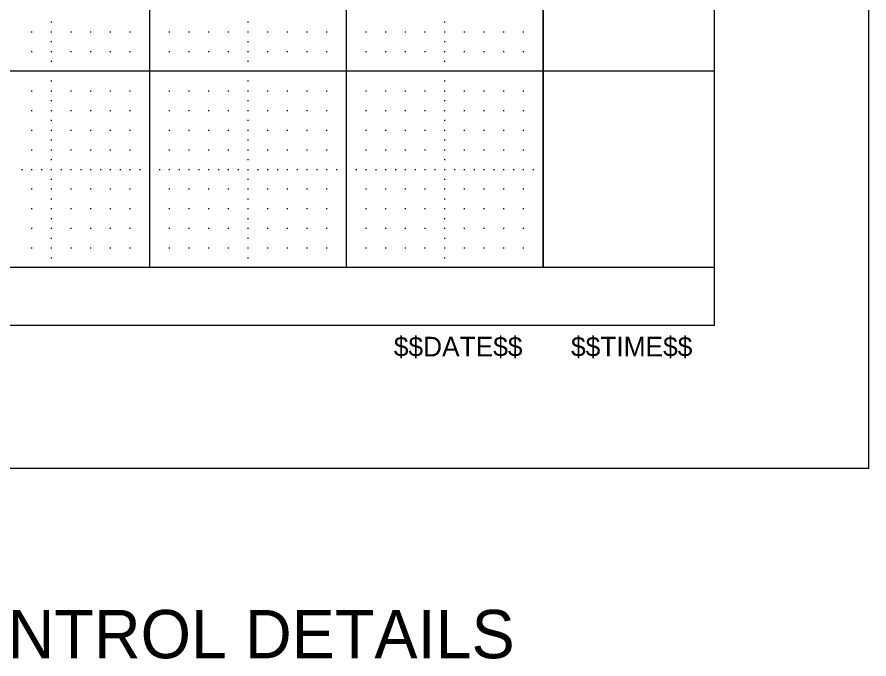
# Model space of a CAD drawing. Extents: x -1.6 to 32.7, y -1.7 to 21.9.
# Drawn here: x 28.07 to 32.402, y -1.698 to 1.568 of the extents above; entities that cross this region are included whole.
import ezdxf

# ---------------------------------------------------------------- set-up
doc = ezdxf.new("R2010")
doc.units = 0
for name, color, linetype in [('Level 1', 7, 'Continuous'), ('Level 4', 7, 'Continuous'), ('Level 48', 7, 'Continuous'), ('Level 5', 7, 'Continuous'), ('Level 63', 7, 'Continuous'), ('R_Border_Dark', 7, 'Continuous'), ('TYPICAL FONT', 7, 'Continuous')]:
    doc.layers.add(name, color=color, linetype=linetype)

msp = doc.modelspace()

# ---------------------------------------------------------------- linework, layer by layer
at = {"layer": 'Level 1'}
for q in [(31.617, 20.545), (-0.001, -0.001)]:
    msp.add_line((31.617, -0.001), q, dxfattribs=at)
msp.add_lwpolyline([(0.745, 11.3072), (30.745, 11.3072), (30.745, 0.293), (0.745, 0.293)], close=True, dxfattribs=at)
at = {"layer": 'Level 4'}
msp.add_line((31.617, 0.293), (-0.001, 0.293), dxfattribs=at)
at = {"layer": 'Level 5'}
for p, q in [((28.2425, 1.543), (28.2475, 1.543)), ((29.2425, 1.543), (29.2475, 1.543)), ((30.2425, 1.543), (30.2475, 1.543)), ((28.1425, 1.493), (28.1475, 1.493)), ((28.2425, 1.493), (28.2475, 1.493)), ((28.3425, 1.493), (28.3475, 1.493)), ((28.4425, 1.493), (28.4475, 1.493)), ((28.5425, 1.493), (28.5475, 1.493)), ((28.6425, 1.493), (28.6475, 1.493)), ((28.8425, 1.493), (28.8475, 1.493)), ((28.9425, 1.493), (28.9475, 1.493)), ((29.0425, 1.493), (29.0475, 1.493)), ((29.1425, 1.493), (29.1475, 1.493)), ((29.2425, 1.493), (29.2475, 1.493)), ((29.3425, 1.493), (29.3475, 1.493)), ((29.4425, 1.493), (29.4475, 1.493)), ((29.5425, 1.493), (29.5475, 1.493)), ((29.6425, 1.493), (29.6475, 1.493)), ((29.8425, 1.493), (29.8475, 1.493)), ((29.9425, 1.493), (29.9475, 1.493)), ((30.0425, 1.493), (30.0475, 1.493)), ((30.1425, 1.493), (30.1475, 1.493)), ((30.2425, 1.493), (30.2475, 1.493)), ((30.3425, 1.493), (30.3475, 1.493)), ((30.4425, 1.493), (30.4475, 1.493)), ((30.5425, 1.493), (30.5475, 1.493)), ((30.6425, 1.493), (30.6475, 1.493)), ((28.2425, 1.443), (28.2475, 1.443)), ((29.2425, 1.443), (29.2475, 1.443)), ((30.2425, 1.443), (30.2475, 1.443)), ((28.1425, 1.393), (28.1475, 1.393)), ((28.2425, 1.393), (28.2475, 1.393)), ((28.3425, 1.393), (28.3475, 1.393)), ((28.4425, 1.393), (28.4475, 1.393)), ((28.5425, 1.393), (28.5475, 1.393)), ((28.6425, 1.393), (28.6475, 1.393)), ((28.8425, 1.393), (28.8475, 1.393)), ((28.9425, 1.393), (28.9475, 1.393)), ((29.0425, 1.393), (29.0475, 1.393)), ((29.1425, 1.393), (29.1475, 1.393)), ((29.2425, 1.393), (29.2475, 1.393)), ((29.3425, 1.393), (29.3475, 1.393)), ((29.4425, 1.393), (29.4475, 1.393)), ((29.5425, 1.393), (29.5475, 1.393)), ((29.6425, 1.393), (29.6475, 1.393)), ((29.8425, 1.393), (29.8475, 1.393)), ((29.9425, 1.393), (29.9475, 1.393)), ((30.0425, 1.393), (30.0475, 1.393)), ((30.1425, 1.393), (30.1475, 1.393)), ((30.2425, 1.393), (30.2475, 1.393)), ((30.3425, 1.393), (30.3475, 1.393)), ((30.4425, 1.393), (30.4475, 1.393)), ((30.5425, 1.393), (30.5475, 1.393)), ((30.6425, 1.393), (30.6475, 1.393)), ((28.2425, 1.343), (28.2475, 1.343)), ((29.2425, 1.343), (29.2475, 1.343)), ((30.2425, 1.343), (30.2475, 1.343)), ((28.2425, 1.243), (28.2475, 1.243)), ((29.2425, 1.243), (29.2475, 1.243)), ((30.2425, 1.243), (30.2475, 1.243)), ((28.1425, 1.193), (28.1475, 1.193)), ((28.2425, 1.193), (28.2475, 1.193)), ((28.3425, 1.193), (28.3475, 1.193)), ((28.4425, 1.193), (28.4475, 1.193)), ((28.5425, 1.193), (28.5475, 1.193)), ((28.6425, 1.193), (28.6475, 1.193)), ((28.8425, 1.193), (28.8475, 1.193)), ((28.9425, 1.193), (28.9475, 1.193)), ((29.0425, 1.193), (29.0475, 1.193)), ((29.1425, 1.193), (29.1475, 1.193)), ((29.2425, 1.193), (29.2475, 1.193)), ((29.3425, 1.193), (29.3475, 1.193)), ((29.4425, 1.193), (29.4475, 1.193)), ((29.5425, 1.193), (29.5475, 1.193)), ((29.6425, 1.193), (29.6475, 1.193)), ((29.8425, 1.193), (29.8475, 1.193)), ((29.9425, 1.193), (29.9475, 1.193)), ((30.0425, 1.193), (30.0475, 1.193)), ((30.1425, 1.193), (30.1475, 1.193)), ((30.2425, 1.193), (30.2475, 1.193)), ((30.3425, 1.193), (30.3475, 1.193)), ((30.4425, 1.193), (30.4475, 1.193)), ((30.5425, 1.193), (30.5475, 1.193)), ((30.6425, 1.193), (30.6475, 1.193)), ((28.2425, 1.143), (28.2475, 1.143)), ((29.2425, 1.143), (29.2475, 1.143)), ((30.2425, 1.143), (30.2475, 1.143)), ((28.1425, 1.093), (28.1475, 1.093)), ((28.2425, 1.093), (28.2475, 1.093)), ((28.3425, 1.093), (28.3475, 1.093)), ((28.4425, 1.093), (28.4475, 1.093)), ((28.5425, 1.093), (28.5475, 1.093)), ((28.6425, 1.093), (28.6475, 1.093)), ((28.8425, 1.093), (28.8475, 1.093)), ((28.9425, 1.093), (28.9475, 1.093)), ((29.0425, 1.093), (29.0475, 1.093)), ((29.1425, 1.093), (29.1475, 1.093)), ((29.2425, 1.093), (29.2475, 1.093)), ((29.3425, 1.093), (29.3475, 1.093)), ((29.4425, 1.093), (29.4475, 1.093)), ((29.5425, 1.093), (29.5475, 1.093)), ((29.6425, 1.093), (29.6475, 1.093)), ((29.8425, 1.093), (29.8475, 1.093)), ((29.9425, 1.093), (29.9475, 1.093)), ((30.0425, 1.093), (30.0475, 1.093)), ((30.1425, 1.093), (30.1475, 1.093)), ((30.2425, 1.093), (30.2475, 1.093)), ((30.3425, 1.093), (30.3475, 1.093)), ((30.4425, 1.093), (30.4475, 1.093)), ((30.5425, 1.093), (30.5475, 1.093)), ((30.6425, 1.093), (30.6475, 1.093)), ((28.2425, 1.043), (28.2475, 1.043)), ((29.2425, 1.043), (29.2475, 1.043)), ((30.2425, 1.043), (30.2475, 1.043)), ((28.1425, 0.993), (28.1475, 0.993)), ((28.2425, 0.993), (28.2475, 0.993)), ((28.3425, 0.993), (28.3475, 0.993)), ((28.4425, 0.993), (28.4475, 0.993)), ((28.5425, 0.993), (28.5475, 0.993)), ((28.6425, 0.993), (28.6475, 0.993)), ((28.8425, 0.993), (28.8475, 0.993)), ((28.9425, 0.993), (28.9475, 0.993)), ((29.0425, 0.993), (29.0475, 0.993)), ((29.1425, 0.993), (29.1475, 0.993)), ((29.2425, 0.993), (29.2475, 0.993)), ((29.3425, 0.993), (29.3475, 0.993)), ((29.4425, 0.993), (29.4475, 0.993)), ((29.5425, 0.993), (29.5475, 0.993)), ((29.6425, 0.993), (29.6475, 0.993)), ((29.8425, 0.993), (29.8475, 0.993)), ((29.9425, 0.993), (29.9475, 0.993)), ((30.0425, 0.993), (30.0475, 0.993)), ((30.1425, 0.993), (30.1475, 0.993)), ((30.2425, 0.993), (30.2475, 0.993)), ((30.3425, 0.993), (30.3475, 0.993)), ((30.4425, 0.993), (30.4475, 0.993)), ((30.5425, 0.993), (30.5475, 0.993)), ((30.6425, 0.993), (30.6475, 0.993)), ((28.2425, 0.943), (28.2475, 0.943)), ((29.2425, 0.943), (29.2475, 0.943)), ((30.2425, 0.943), (30.2475, 0.943)), ((28.1425, 0.893), (28.1475, 0.893)), ((28.2425, 0.893), (28.2475, 0.893)), ((28.3425, 0.893), (28.3475, 0.893)), ((28.4425, 0.893), (28.4475, 0.893)), ((28.5425, 0.893), (28.5475, 0.893)), ((28.6425, 0.893), (28.6475, 0.893)), ((28.8425, 0.893), (28.8475, 0.893)), ((28.9425, 0.893), (28.9475, 0.893)), ((29.0425, 0.893), (29.0475, 0.893)), ((29.1425, 0.893), (29.1475, 0.893)), ((29.2425, 0.893), (29.2475, 0.893)), ((29.3425, 0.893), (29.3475, 0.893)), ((29.4425, 0.893), (29.4475, 0.893)), ((29.5425, 0.893), (29.5475, 0.893)), ((29.6425, 0.893), (29.6475, 0.893)), ((29.8425, 0.893), (29.8475, 0.893)), ((29.9425, 0.893), (29.9475, 0.893)), ((30.0425, 0.893), (30.0475, 0.893)), ((30.1425, 0.893), (30.1475, 0.893)), ((30.2425, 0.893), (30.2475, 0.893)), ((30.3425, 0.893), (30.3475, 0.893)), ((30.4425, 0.893), (30.4475, 0.893)), ((30.5425, 0.893), (30.5475, 0.893)), ((30.6425, 0.893), (30.6475, 0.893)), ((28.2425, 0.843), (28.2475, 0.843)), ((29.2425, 0.843), (29.2475, 0.843)), ((30.2425, 0.843), (30.2475, 0.843)), ((28.0925, 0.793), (28.0975, 0.793)), ((28.1425, 0.793), (28.1475, 0.793)), ((28.1925, 0.793), (28.1975, 0.793)), ((28.2425, 0.793), (28.2475, 0.793)), ((28.2925, 0.793), (28.2975, 0.793)), ((28.3425, 0.793), (28.3475, 0.793)), ((28.3925, 0.793), (28.3975, 0.793)), ((28.4425, 0.793), (28.4475, 0.793)), ((28.4925, 0.793), (28.4975, 0.793)), ((28.5425, 0.793), (28.5475, 0.793)), ((28.5925, 0.793), (28.5975, 0.793)), ((28.6425, 0.793), (28.6475, 0.793)), ((28.6925, 0.793), (28.6975, 0.793)), ((28.7925, 0.793), (28.7975, 0.793)), ((28.8425, 0.793), (28.8475, 0.793)), ((28.8925, 0.793), (28.8975, 0.793)), ((28.9425, 0.793), (28.9475, 0.793)), ((28.9925, 0.793), (28.9975, 0.793)), ((29.0425, 0.793), (29.0475, 0.793)), ((29.0925, 0.793), (29.0975, 0.793)), ((29.1425, 0.793), (29.1475, 0.793)), ((29.1925, 0.793), (29.1975, 0.793)), ((29.2425, 0.793), (29.2475, 0.793)), ((29.2925, 0.793), (29.2975, 0.793)), ((29.3425, 0.793), (29.3475, 0.793)), ((29.3925, 0.793), (29.3975, 0.793)), ((29.4425, 0.793), (29.4475, 0.793)), ((29.4925, 0.793), (29.4975, 0.793)), ((29.5425, 0.793), (29.5475, 0.793)), ((29.5925, 0.793), (29.5975, 0.793)), ((29.6425, 0.793), (29.6475, 0.793)), ((29.6925, 0.793), (29.6975, 0.793)), ((29.7925, 0.793), (29.7975, 0.793)), ((29.8425, 0.793), (29.8475, 0.793)), ((29.8925, 0.793), (29.8975, 0.793)), ((29.9425, 0.793), (29.9475, 0.793)), ((29.9925, 0.793), (29.9975, 0.793)), ((30.0425, 0.793), (30.0475, 0.793)), ((30.0925, 0.793), (30.0975, 0.793)), ((30.1425, 0.793), (30.1475, 0.793)), ((30.1925, 0.793), (30.1975, 0.793)), ((30.2425, 0.793), (30.2475, 0.793)), ((30.2925, 0.793), (30.2975, 0.793)), ((30.3425, 0.793), (30.3475, 0.793)), ((30.3925, 0.793), (30.3975, 0.793)), ((30.4425, 0.793), (30.4475, 0.793)), ((30.4925, 0.793), (30.4975, 0.793)), ((30.5425, 0.793), (30.5475, 0.793)), ((30.5925, 0.793), (30.5975, 0.793)), ((30.6425, 0.793), (30.6475, 0.793)), ((30.6925, 0.793), (30.6975, 0.793)), ((28.2425, 0.743), (28.2475, 0.743)), ((29.2425, 0.743), (29.2475, 0.743)), ((30.2425, 0.743), (30.2475, 0.743)), ((28.1425, 0.693), (28.1475, 0.693)), ((28.2425, 0.693), (28.2475, 0.693)), ((28.3425, 0.693), (28.3475, 0.693)), ((28.4425, 0.693), (28.4475, 0.693)), ((28.5425, 0.693), (28.5475, 0.693)), ((28.6425, 0.693), (28.6475, 0.693)), ((28.8425, 0.693), (28.8475, 0.693)), ((28.9425, 0.693), (28.9475, 0.693)), ((29.0425, 0.693), (29.0475, 0.693)), ((29.1425, 0.693), (29.1475, 0.693)), ((29.2425, 0.693), (29.2475, 0.693)), ((29.3425, 0.693), (29.3475, 0.693)), ((29.4425, 0.693), (29.4475, 0.693)), ((29.5425, 0.693), (29.5475, 0.693)), ((29.6425, 0.693), (29.6475, 0.693)), ((29.8425, 0.693), (29.8475, 0.693)), ((29.9425, 0.693), (29.9475, 0.693)), ((30.0425, 0.693), (30.0475, 0.693)), ((30.1425, 0.693), (30.1475, 0.693)), ((30.2425, 0.693), (30.2475, 0.693)), ((30.3425, 0.693), (30.3475, 0.693)), ((30.4425, 0.693), (30.4475, 0.693)), ((30.5425, 0.693), (30.5475, 0.693)), ((30.6425, 0.693), (30.6475, 0.693)), ((28.2425, 0.643), (28.2475, 0.643)), ((29.2425, 0.643), (29.2475, 0.643)), ((30.2425, 0.643), (30.2475, 0.643)), ((28.1425, 0.593), (28.1475, 0.593)), ((28.2425, 0.593), (28.2475, 0.593)), ((28.3425, 0.593), (28.3475, 0.593)), ((28.4425, 0.593), (28.4475, 0.593)), ((28.5425, 0.593), (28.5475, 0.593)), ((28.6425, 0.593), (28.6475, 0.593)), ((28.8425, 0.593), (28.8475, 0.593)), ((28.9425, 0.593), (28.9475, 0.593)), ((29.0425, 0.593), (29.0475, 0.593)), ((29.1425, 0.593), (29.1475, 0.593)), ((29.2425, 0.593), (29.2475, 0.593)), ((29.3425, 0.593), (29.3475, 0.593)), ((29.4425, 0.593), (29.4475, 0.593)), ((29.5425, 0.593), (29.5475, 0.593)), ((29.6425, 0.593), (29.6475, 0.593)), ((29.8425, 0.593), (29.8475, 0.593)), ((29.9425, 0.593), (29.9475, 0.593)), ((30.0425, 0.593), (30.0475, 0.593)), ((30.1425, 0.593), (30.1475, 0.593)), ((30.2425, 0.593), (30.2475, 0.593)), ((30.3425, 0.593), (30.3475, 0.593)), ((30.4425, 0.593), (30.4475, 0.593)), ((30.5425, 0.593), (30.5475, 0.593)), ((30.6425, 0.593), (30.6475, 0.593)), ((28.2425, 0.543), (28.2475, 0.543)), ((29.2425, 0.543), (29.2475, 0.543)), ((30.2425, 0.543), (30.2475, 0.543)), ((28.1425, 0.493), (28.1475, 0.493)), ((28.2425, 0.493), (28.2475, 0.493)), ((28.3425, 0.493), (28.3475, 0.493)), ((28.4425, 0.493), (28.4475, 0.493)), ((28.5425, 0.493), (28.5475, 0.493)), ((28.6425, 0.493), (28.6475, 0.493)), ((28.8425, 0.493), (28.8475, 0.493)), ((28.9425, 0.493), (28.9475, 0.493)), ((29.0425, 0.493), (29.0475, 0.493)), ((29.1425, 0.493), (29.1475, 0.493)), ((29.2425, 0.493), (29.2475, 0.493)), ((29.3425, 0.493), (29.3475, 0.493)), ((29.4425, 0.493), (29.4475, 0.493)), ((29.5425, 0.493), (29.5475, 0.493)), ((29.6425, 0.493), (29.6475, 0.493)), ((29.8425, 0.493), (29.8475, 0.493)), ((29.9425, 0.493), (29.9475, 0.493)), ((30.0425, 0.493), (30.0475, 0.493)), ((30.1425, 0.493), (30.1475, 0.493)), ((30.2425, 0.493), (30.2475, 0.493)), ((30.3425, 0.493), (30.3475, 0.493)), ((30.4425, 0.493), (30.4475, 0.493)), ((30.5425, 0.493), (30.5475, 0.493)), ((30.6425, 0.493), (30.6475, 0.493)), ((28.2425, 0.443), (28.2475, 0.443)), ((29.2425, 0.443), (29.2475, 0.443)), ((30.2425, 0.443), (30.2475, 0.443)), ((28.1425, 0.393), (28.1475, 0.393)), ((28.2425, 0.393), (28.2475, 0.393)), ((28.3425, 0.393), (28.3475, 0.393)), ((28.4425, 0.393), (28.4475, 0.393)), ((28.5425, 0.393), (28.5475, 0.393)), ((28.6425, 0.393), (28.6475, 0.393)), ((28.8425, 0.393), (28.8475, 0.393)), ((28.9425, 0.393), (28.9475, 0.393)), ((29.0425, 0.393), (29.0475, 0.393)), ((29.1425, 0.393), (29.1475, 0.393)), ((29.2425, 0.393), (29.2475, 0.393)), ((29.3425, 0.393), (29.3475, 0.393)), ((29.4425, 0.393), (29.4475, 0.393)), ((29.5425, 0.393), (29.5475, 0.393)), ((29.6425, 0.393), (29.6475, 0.393)), ((29.8425, 0.393), (29.8475, 0.393)), ((29.9425, 0.393), (29.9475, 0.393)), ((30.0425, 0.393), (30.0475, 0.393)), ((30.1425, 0.393), (30.1475, 0.393)), ((30.2425, 0.393), (30.2475, 0.393)), ((30.3425, 0.393), (30.3475, 0.393)), ((30.4425, 0.393), (30.4475, 0.393)), ((30.5425, 0.393), (30.5475, 0.393)), ((30.6425, 0.393), (30.6475, 0.393)), ((28.2425, 0.343), (28.2475, 0.343)), ((29.2425, 0.343), (29.2475, 0.343)), ((30.2425, 0.343), (30.2475, 0.343))]:
    msp.add_line(p, q, dxfattribs=at)
at = {"layer": 'Level 63'}
msp.add_lwpolyline([(-1.598, -0.727), (32.402, -0.727), (32.402, 21.273), (-1.598, 21.273)], close=True, dxfattribs=at)
msp.add_lwpolyline([(30.745, 8.293), (30.745, 0.293), (0.745, 0.293), (0.745, 8.293)], dxfattribs=at)
at = {"layer": 'R_Border_Dark'}
for p, q in [((28.745, 0.293), (28.745, 11.3072)), ((29.745, 0.293), (29.745, 11.3072)), ((30.745, 0.293), (30.745, 8.293)), ((31.617, 1.293), (-0.001, 1.293))]:
    msp.add_line(p, q, dxfattribs=at)
msp.add_lwpolyline([(30.745, 8.293), (30.745, 0.293), (0.745, 0.293), (0.745, 8.293)], dxfattribs=at)

# ---------------------------------------------------------------- texts
at = {"layer": 'Level 48'}
for s, p in [('$$DATE$$', (29.986, -0.159)), ('$$TIME$$', (30.887, -0.159))]:
    msp.add_text(s, height=0.1, dxfattribs=at).set_placement(p)
at = {"layer": 'TYPICAL FONT'}
msp.add_text('TEMPORARY EROSION CONTROL DETAILS', height=0.246094, dxfattribs=at).set_placement((23.7436, -1.6948))

doc.saveas('drawing.dxf')
